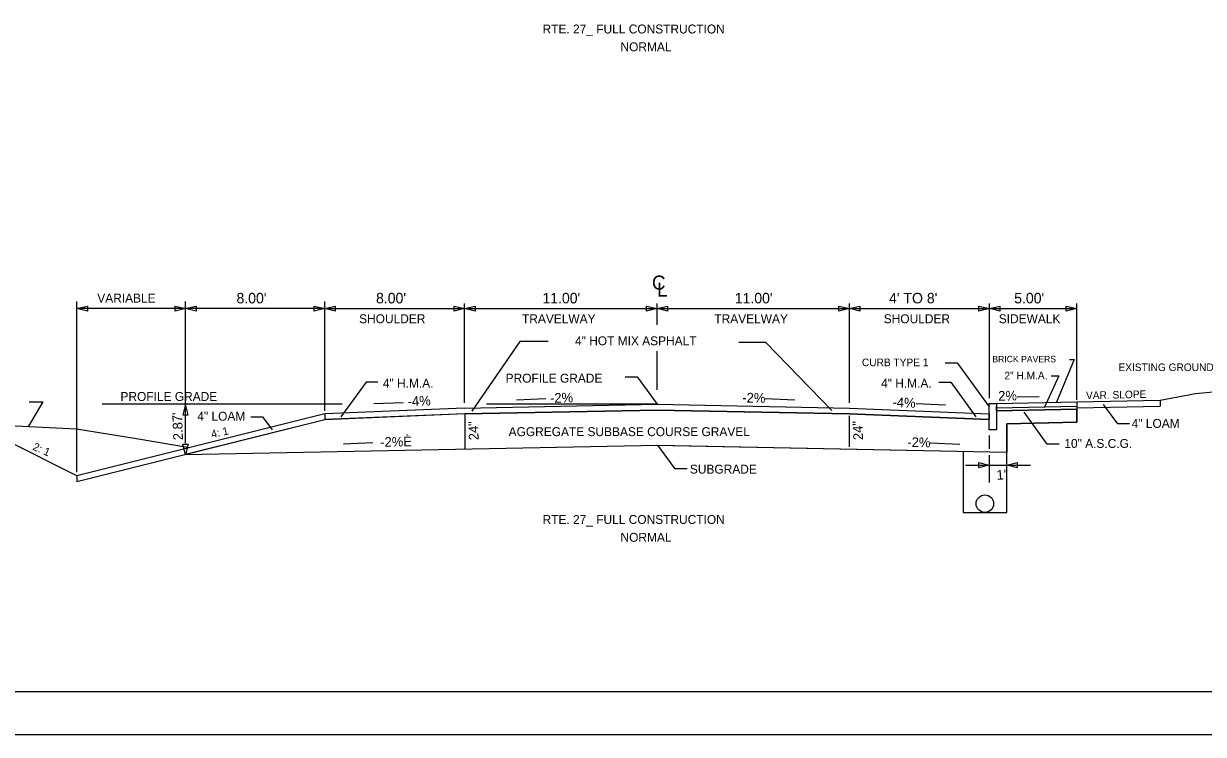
# Model space of a CAD drawing. Extents: x -60 to 130, y -2 to 86.
# Drawn here: x 7.9 to 75.3, y -2.4 to 38.2 of the extents above; entities that cross this region are included whole.
import ezdxf

# ---------------------------------------------------------------- set-up
doc = ezdxf.new("R2010")
doc.units = 0
for name, color, linetype in [('ANNOTATION', 7, 'Continuous'), ('BORDER', 7, 'Continuous'), ('D_Curb_Type1_Rt', 7, 'Continuous'), ('D_Curb_Type_1_Rt', 7, 'Continuous'), ('D_Roadway_Edge_Shoulder', 7, 'Continuous'), ('D_Roadway_Edge_TW', 7, 'Continuous'), ('D_Roadway_FinishedGrade', 7, 'Continuous'), ('D_Roadway_Sidewalks_Paved', 7, 'Continuous'), ('D_Roadway_SubGrade', 7, 'Continuous'), ('DIMENSIONS', 7, 'Continuous'), ('PATTERNING', 7, 'Continuous'), ('PDRAIN', 7, 'Continuous'), ('PLOT BOUNDARY', 7, 'Continuous'), ('S_Roadway_Centerline', 7, 'Continuous')]:
    doc.layers.add(name, color=color, linetype=linetype)

msp = doc.modelspace()

# ---------------------------------------------------------------- linework, layer by layer
at = {"layer": 'ANNOTATION'}
for p, q in [((64.696, 16.849), (65.941, 16.874)), ((29.576, 16.51), (27.893, 16.443)), ((37.74, 16.736), (36.056, 16.668)), ((50.284, 16.756), (51.968, 16.689)), ((58.908, 16.471), (60.592, 16.404)), ((27.841, 14.218), (26.157, 14.151)), ((59.723, 14.213), (61.406, 14.146))]:
    msp.add_line(p, q, dxfattribs=at)
for points in [[(37.873, 20.015), (36.254, 20.015), (33.497, 16.042)], [(48.778, 19.968), (50.301, 19.968), (54.085, 16.069)], [(67.682, 18.988), (67.946, 18.988), (66.931, 16.54)], [(60.578, 18.799), (61.259, 18.799), (63.096, 16.282)], [(28.134, 17.683), (27.454, 17.683), (26.018, 15.715)], [(42.274, 17.987), (42.954, 17.987), (44.093, 16.428)], [(60.207, 17.683), (60.887, 17.683), (62.324, 15.715)], [(66.642, 18.046), (67.069, 18.046), (66.228, 16.225)], [(8.181, 16.569), (8.969, 16.569), (8.159, 15.166)], [(71.117, 15.307), (70.436, 15.307), (69.623, 16.42)], [(20.857, 15.717), (21.537, 15.717), (22.086, 14.965)], [(67.087, 14.155), (66.407, 14.155), (65.082, 15.969)], [(45.813, 12.735), (45.133, 12.735), (44.139, 14.095)]]:
    msp.add_lwpolyline(points, dxfattribs=at)
at = {"layer": 'BORDER'}
msp.add_line((0, 0), (128, 0), dxfattribs=at)
at = {"layer": 'D_Curb_Type1_Rt'}
msp.add_lwpolyline([(63.509, 16.472), (63.509, 14.972), (63.093, 14.972), (63.093, 16.472)], close=True, dxfattribs=at)
at = {"layer": 'D_Curb_Type_1_Rt'}
msp.add_line((63.509, 14.972), (63.093, 14.972), dxfattribs=at)
at = {"layer": 'D_Roadway_Edge_Shoulder'}
for p, q in [((33.093, 16.208), (25.093, 15.888)), ((55.093, 16.208), (63.093, 15.888)), ((25.093, 15.888), (25.093, 15.545)), ((33.106, 15.875), (25.093, 15.555)), ((55.079, 15.875), (63.093, 15.555)), ((63.093, 15.888), (63.093, 15.555))]:
    msp.add_line(p, q, dxfattribs=at)
at = {"layer": 'D_Roadway_Edge_TW'}
for p, q in [((33.093, 16.208), (44.093, 16.428)), ((44.093, 16.428), (55.093, 16.208)), ((33.099, 15.875), (44.099, 16.095)), ((44.086, 16.095), (55.086, 15.875))]:
    msp.add_line(p, q, dxfattribs=at)
at = {"layer": 'D_Roadway_FinishedGrade'}
for p, q in [((68.098, 16.563), (72.871, 16.659)), ((68.104, 16.23), (72.871, 16.326)), ((72.871, 16.659), (72.871, 16.326)), ((25.093, 15.888), (10.919, 12.345)), ((25.093, 15.545), (10.919, 12.001)), ((10.919, 12.345), (6.849, 14.379)), ((10.919, 12.345), (10.919, 12.001))]:
    msp.add_line(p, q, dxfattribs=at)
at = {"layer": 'D_Roadway_Sidewalks_Paved'}
for p, q in [((63.509, 16.472), (68.098, 16.563)), ((63.509, 16.221), (68.098, 16.313)), ((63.509, 16.055), (68.098, 16.147))]:
    msp.add_line(p, q, dxfattribs=at)
at = {"layer": 'D_Roadway_SubGrade'}
for p, q in [((68.098, 16.563), (68.098, 15.397)), ((68.098, 15.397), (64.093, 15.316)), ((64.093, 15.316), (64.093, 13.694)), ((17.134, 13.555), (44.139, 14.095)), ((44.046, 14.095), (64.093, 13.694))]:
    msp.add_line(p, q, dxfattribs=at)
at = {"layer": 'DIMENSIONS'}
for p, q in [((10.919, 12.545), (10.919, 22.295)), ((17.134, 14.21), (17.134, 22.295)), ((25.093, 16.047), (25.093, 22.295)), ((25.093, 16.283), (25.093, 22.295)), ((17.134, 21.895), (10.919, 21.895)), ((25.093, 21.895), (17.134, 21.895)), ((25.093, 21.895), (17.134, 21.895)), ((25.093, 16.508), (25.093, 22.195)), ((25.093, 21.895), (33.093, 21.895)), ((33.093, 16.508), (33.093, 22.195)), ((33.093, 21.895), (44.093, 21.895)), ((44.093, 20.959), (44.093, 22.195)), ((44.093, 21.895), (55.093, 21.895)), ((55.093, 16.508), (55.093, 22.195)), ((55.093, 21.895), (63.098, 21.895)), ((63.098, 16.772), (63.098, 22.195)), ((63.098, 21.895), (68.098, 21.895)), ((66.738, 21.895), (68.098, 21.895)), ((68.098, 16.863), (68.098, 22.195)), ((68.098, 16.687), (68.098, 22.195)), ((44.093, 17.25), (44.093, 19.462)), ((26.088, 16.428), (12.367, 16.428)), ((44.093, 16.428), (34.338, 16.428)), ((33.099, 15.875), (33.099, 13.875)), ((55.079, 15.76), (55.079, 14)), ((63.085, 14.65), (63.085, 13.875)), ((63.093, 13.52), (63.093, 11.948)), ((61.733, 12.952), (63.093, 12.952)), ((63.093, 12.952), (64.093, 12.952)), ((64.093, 12.952), (65.453, 12.952))]:
    msp.add_line(p, q, dxfattribs=at)
for points in [[(11.519, 21.745), (10.919, 21.895), (11.519, 22.045)], [(16.534, 22.045), (17.134, 21.895), (16.534, 21.745)], [(17.734, 21.745), (17.134, 21.895), (17.734, 22.045)], [(24.493, 22.045), (25.093, 21.895), (24.493, 21.745)], [(24.493, 22.045), (25.093, 21.895), (24.493, 21.745)], [(25.693, 21.745), (25.093, 21.895), (25.693, 22.045)], [(32.493, 22.045), (33.093, 21.895), (32.493, 21.745)], [(33.693, 21.745), (33.093, 21.895), (33.693, 22.045)], [(43.493, 22.045), (44.093, 21.895), (43.493, 21.745)], [(44.693, 21.745), (44.093, 21.895), (44.693, 22.045)], [(54.493, 22.045), (55.093, 21.895), (54.493, 21.745)], [(55.693, 21.745), (55.093, 21.895), (55.693, 22.045)], [(62.498, 22.045), (63.098, 21.895), (62.498, 21.745)], [(63.698, 21.745), (63.098, 21.895), (63.698, 22.045)], [(67.498, 22.045), (68.098, 21.895), (67.498, 21.745)], [(17.284, 15.828), (17.134, 16.428), (16.984, 15.828)], [(17.284, 14.155), (17.134, 13.555), (16.984, 14.155)], [(62.493, 13.102), (63.093, 12.952), (62.493, 12.802)], [(64.693, 12.802), (64.093, 12.952), (64.693, 13.102)]]:
    msp.add_lwpolyline(points, close=True, dxfattribs=at)
at = {"layer": 'PATTERNING'}
for points in [[(63.509, 16.305), (63.509, 14.972), (63.093, 14.972), (63.093, 15.555), (55.086, 15.875), (44.099, 16.095), (33.106, 15.875), (25.093, 15.545), (17.134, 13.555), (44.139, 14.095), (64.093, 13.694), (64.093, 15.316), (68.098, 15.397), (68.098, 16.147), (63.509, 16.055)], [(63.509, 16.055), (63.509, 14.972), (63.093, 14.972), (63.093, 15.555), (55.086, 15.875), (44.099, 16.095), (33.106, 15.875), (25.093, 15.555), (25.093, 15.545), (17.134, 13.555), (44.139, 14.095), (64.093, 13.694), (64.093, 15.316), (68.098, 15.397), (68.098, 16.147), (63.509, 16.055)]]:
    msp.add_lwpolyline(points, close=True, dxfattribs=at)
at = {"layer": 'PDRAIN'}
msp.add_lwpolyline([(61.593, 13.744), (61.593, 10.243), (64.093, 10.243), (64.093, 13.694)], dxfattribs=at)
msp.add_circle((62.843, 10.743), 0.5, dxfattribs=at)
at = {"layer": 'PLOT BOUNDARY'}
msp.add_lwpolyline([(-6.475, -2.447), (129.525, -2.447), (129.525, 85.553), (-6.475, 85.553)], close=True, dxfattribs=at)
at = {"layer": 'S_Roadway_Centerline'}
for points in [[(72.871, 16.659), (74.887, 17.051), (76.503, 17.192), (77.544, 17.409), (79.799, 18.233)], [(0, 15.564), (10.906, 15.032), (14.329, 14.462), (17.364, 13.956)]]:
    msp.add_lwpolyline(points, dxfattribs=at)

# ---------------------------------------------------------------- texts
at = {"layer": 'ANNOTATION'}
for s, height, p in [('RTE. 27_ FULL CONSTRUCTION', 0.51, (37.548, 37.627)), ('NORMAL', 0.51, (42.006, 36.607)), ('C', 0.805, (43.804, 22.981)), ('L', 0.805, (44.093, 22.579)), ("8.00'", 0.6, (28.025, 22.195)), ("11.00'", 0.6, (37.541, 22.195)), ("11.00'", 0.6, (48.541, 22.195)), ("4' TO 8'", 0.6, (57.365, 22.195)), ("5.00'", 0.6, (64.519, 22.195)), ('SHOULDER', 0.51, (27.058, 21.061)), ('TRAVELWAY', 0.51, (36.372, 21.061)), ('TRAVELWAY', 0.51, (47.372, 21.061)), ('SHOULDER', 0.51, (57.06, 21.061)), ('SIDEWALK', 0.51, (63.636, 21.061)), ('4" HOT MIX ASPHALT', 0.51, (39.405, 19.799)), ('CURB TYPE 1', 0.4335, (55.811, 18.605)), ('BRICK PAVERS', 0.36847, (63.27, 18.827)), ('2" H.M.A.', 0.4335, (63.959, 17.85)), ('EXISTING GROUND', 0.4335, (70.482, 18.325)), ('4" H.M.A.', 0.51, (28.415, 17.374)), ('PROFILE GRADE', 0.51, (35.436, 17.665)), ('4" H.M.A.', 0.51, (56.906, 17.374)), ('PROFILE GRADE', 0.51, (13.412, 16.617)), ('4" LOAM', 0.51, (17.805, 15.487)), ('4" LOAM', 0.51, (71.236, 15.079)), ('AGGREGATE SUBBASE COURSE GRAVEL', 0.51, (35.609, 14.606)), ('10" A.S.C.G.', 0.51, (67.387, 13.932)), ('SUBGRADE', 0.51, (45.973, 12.463)), ('RTE. 27_ FULL CONSTRUCTION', 0.51, (37.548, 9.585)), ('NORMAL', 0.51, (42.006, 8.565))]:
    msp.add_text(s, height=height, dxfattribs=at).set_placement(p)
for s, height, rotation, p in [('-4%', 0.5541, 2.29061, (29.844, 16.31)), ('-2%', 0.5541, 1.14576, (37.979, 16.509)), ('-2%', 0.5541, 358.85424, (48.968, 16.534)), ('2%', 0.5541, 1.14576, (63.61, 16.63)), ('VAR. SLOPE', 0.4335, 1.2943, (68.631, 16.715)), ('-4%', 0.5541, 357.70939, (57.551, 16.275)), ("2.87'", 0.5541, 92.29061, (16.988, 14.384)), ('4: 1', 0.45, 12.67252, (18.647, 14.487)), ('24"', 0.5541, 92.29061, (33.896, 14.385)), ('24"', 0.5541, 92.29061, (55.876, 14.393)), ('2: 1', 0.45, 336.60784, (8.352, 13.84)), ('-2%È', 0.5541, 1.14576, (28.269, 13.988)), ('-2%', 0.5541, 358.85424, (58.406, 13.991)), ("1'", 0.5541, 2.29061, (63.519, 12.113))]:
    msp.add_text(s, height=height, rotation=rotation, dxfattribs=at).set_placement(p)
at = {"layer": 'DIMENSIONS'}
for s, height, p in [('VARIABLE', 0.51, (12.085, 22.24)), ("8.00'", 0.6, (20.046, 22.195))]:
    msp.add_text(s, height=height, dxfattribs=at).set_placement(p)

doc.saveas('drawing.dxf')
